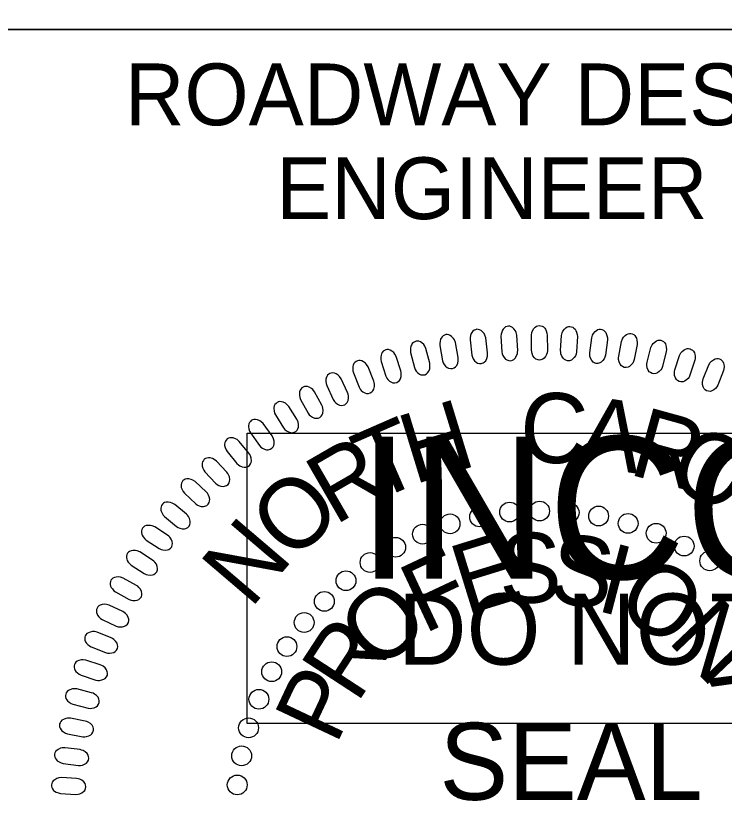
# Model space of a CAD drawing. Extents: x 505602 to 507286, y 483109 to 484209.
# Drawn here: x 507076.9 to 507134.2, y 484096 to 484159.8 of the extents above; entities that cross this region are included whole.
import ezdxf

# ---------------------------------------------------------------- set-up
doc = ezdxf.new("R2010")
doc.units = 0
for name, color, linetype in [('Sheet PE Seal Cell', 7, 'Continuous'), ('Sheet Profile CELL', 7, 'Continuous'), ('Sheet Sticker Incomplete CELL', 7, 'Continuous')]:
    doc.layers.add(name, color=color, linetype=linetype)

msp = doc.modelspace()

# ---------------------------------------------------------------- linework, layer by layer
at = {"layer": 'Sheet PE Seal Cell'}
for points in [[(507115.061, 484132.495), (507114.908, 484133.712), (507114.844, 484133.925), (507114.774, 484134.057), (507114.642, 484134.211), (507114.531, 484134.308), (507114.411, 484134.373), (507114.301, 484134.399), (507114.187, 484134.405), (507114.079, 484134.371), (507113.964, 484134.327), (507113.868, 484134.254), (507113.776, 484134.142), (507113.727, 484134.056), (507113.679, 484133.899), (507113.642, 484133.713), (507113.64, 484133.552), (507113.79, 484132.305), (507113.833, 484132.139), (507113.895, 484132.006), (507114.003, 484131.859), (507114.132, 484131.735), (507114.239, 484131.668), (507114.402, 484131.627), (507114.553, 484131.626), (507114.696, 484131.685), (507114.794, 484131.748), (507114.907, 484131.862), (507115.005, 484132.045), (507115.049, 484132.232), (507115.062, 484132.364)], [(507117.5, 484132.697), (507117.423, 484133.922), (507117.372, 484134.138), (507117.311, 484134.274), (507117.188, 484134.437), (507117.085, 484134.54), (507116.968, 484134.613), (507116.861, 484134.646), (507116.747, 484134.659), (507116.637, 484134.632), (507116.52, 484134.595), (507116.419, 484134.529), (507116.321, 484134.422), (507116.266, 484134.339), (507116.208, 484134.185), (507116.159, 484134.003), (507116.147, 484133.842), (507116.218, 484132.587), (507116.251, 484132.42), (507116.305, 484132.283), (507116.404, 484132.129), (507116.525, 484131.997), (507116.626, 484131.923), (507116.787, 484131.873), (507116.938, 484131.863), (507117.085, 484131.912), (507117.186, 484131.969), (507117.306, 484132.076), (507117.415, 484132.252), (507117.471, 484132.436), (507117.493, 484132.567)], [(507118.615, 484132.706), (507118.615, 484133.933), (507118.653, 484134.152), (507118.705, 484134.293), (507118.817, 484134.462), (507118.915, 484134.571), (507119.027, 484134.651), (507119.131, 484134.691), (507119.244, 484134.711), (507119.355, 484134.691), (507119.475, 484134.661), (507119.58, 484134.601), (507119.684, 484134.501), (507119.744, 484134.421), (507119.811, 484134.272), (507119.871, 484134.092), (507119.894, 484133.933), (507119.901, 484132.676), (507119.878, 484132.507), (507119.833, 484132.367), (507119.744, 484132.208), (507119.631, 484132.067), (507119.534, 484131.988), (507119.377, 484131.928), (507119.228, 484131.909), (507119.078, 484131.948), (507118.974, 484131.998), (507118.846, 484132.098), (507118.727, 484132.268), (507118.66, 484132.447), (507118.63, 484132.577)], [(507120.974, 484132.68), (507121.051, 484133.904), (507121.102, 484134.121), (507121.163, 484134.257), (507121.286, 484134.419), (507121.39, 484134.522), (507121.507, 484134.595), (507121.614, 484134.628), (507121.727, 484134.641), (507121.838, 484134.614), (507121.955, 484134.576), (507122.056, 484134.51), (507122.154, 484134.404), (507122.209, 484134.321), (507122.267, 484134.167), (507122.315, 484133.984), (507122.327, 484133.824), (507122.255, 484132.569), (507122.222, 484132.401), (507122.169, 484132.265), (507122.069, 484132.111), (507121.948, 484131.979), (507121.846, 484131.905), (507121.686, 484131.855), (507121.535, 484131.845), (507121.389, 484131.894), (507121.287, 484131.951), (507121.167, 484132.058), (507121.059, 484132.235), (507121.002, 484132.418), (507120.981, 484132.55)], [(507123.336, 484132.505), (507123.491, 484133.722), (507123.555, 484133.935), (507123.625, 484134.066), (507123.757, 484134.221), (507123.868, 484134.318), (507123.989, 484134.382), (507124.097, 484134.409), (507124.211, 484134.415), (507124.32, 484134.38), (507124.434, 484134.336), (507124.531, 484134.263), (507124.622, 484134.151), (507124.672, 484134.065), (507124.72, 484133.908), (507124.756, 484133.722), (507124.759, 484133.561), (507124.608, 484132.313), (507124.564, 484132.148), (507124.503, 484132.016), (507124.394, 484131.868), (507124.265, 484131.744), (507124.159, 484131.677), (507123.995, 484131.637), (507123.844, 484131.636), (507123.701, 484131.695), (507123.603, 484131.757), (507123.489, 484131.872), (507123.392, 484132.055), (507123.348, 484132.242), (507123.335, 484132.375)], [(507112.68, 484132.127), (507112.451, 484133.331), (507112.373, 484133.54), (507112.296, 484133.668), (507112.153, 484133.813), (507112.038, 484133.903), (507111.913, 484133.96), (507111.803, 484133.98), (507111.688, 484133.979), (507111.582, 484133.938), (507111.47, 484133.886), (507111.378, 484133.808), (507111.294, 484133.69), (507111.25, 484133.6), (507111.213, 484133.441), (507111.187, 484133.254), (507111.195, 484133.093), (507111.423, 484131.857), (507111.476, 484131.694), (507111.546, 484131.566), (507111.665, 484131.426), (507111.801, 484131.309), (507111.911, 484131.249), (507112.077, 484131.22), (507112.227, 484131.229), (507112.367, 484131.296), (507112.46, 484131.364), (507112.566, 484131.486), (507112.652, 484131.674), (507112.685, 484131.864), (507112.689, 484131.996)], [(507125.676, 484132.219), (507125.906, 484133.423), (507125.984, 484133.632), (507126.062, 484133.759), (507126.204, 484133.904), (507126.319, 484133.994), (507126.444, 484134.051), (507126.555, 484134.071), (507126.669, 484134.07), (507126.775, 484134.029), (507126.887, 484133.977), (507126.979, 484133.898), (507127.063, 484133.781), (507127.106, 484133.692), (507127.144, 484133.532), (507127.17, 484133.344), (507127.162, 484133.183), (507126.933, 484131.947), (507126.879, 484131.785), (507126.809, 484131.657), (507126.691, 484131.517), (507126.554, 484131.401), (507126.444, 484131.34), (507126.279, 484131.311), (507126.128, 484131.32), (507125.989, 484131.387), (507125.896, 484131.455), (507125.789, 484131.577), (507125.704, 484131.766), (507125.671, 484131.955), (507125.666, 484132.088)], [(507110.375, 484131.654), (507110.07, 484132.843), (507109.98, 484133.046), (507109.894, 484133.169), (507109.743, 484133.305), (507109.622, 484133.387), (507109.494, 484133.436), (507109.382, 484133.449), (507109.269, 484133.441), (507109.165, 484133.394), (507109.057, 484133.335), (507108.97, 484133.251), (507108.893, 484133.128), (507108.855, 484133.036), (507108.827, 484132.874), (507108.814, 484132.686), (507108.832, 484132.526), (507109.137, 484131.306), (507109.2, 484131.148), (507109.279, 484131.024), (507109.405, 484130.891), (507109.549, 484130.784), (507109.662, 484130.731), (507109.83, 484130.711), (507109.979, 484130.73), (507110.114, 484130.805), (507110.203, 484130.879), (507110.301, 484131.008), (507110.375, 484131.202), (507110.396, 484131.393), (507110.392, 484131.525)], [(507127.981, 484131.745), (507128.286, 484132.933), (507128.377, 484133.135), (507128.463, 484133.258), (507128.614, 484133.395), (507128.735, 484133.476), (507128.863, 484133.526), (507128.975, 484133.538), (507129.089, 484133.53), (507129.192, 484133.483), (507129.3, 484133.424), (507129.387, 484133.34), (507129.463, 484133.217), (507129.501, 484133.125), (507129.529, 484132.963), (507129.543, 484132.775), (507129.525, 484132.614), (507129.219, 484131.395), (507129.154, 484131.237), (507129.076, 484131.113), (507128.95, 484130.981), (507128.806, 484130.873), (507128.693, 484130.82), (507128.526, 484130.801), (507128.376, 484130.819), (507128.241, 484130.896), (507128.152, 484130.97), (507128.054, 484131.098), (507127.98, 484131.292), (507127.96, 484131.482), (507127.963, 484131.615)], [(507108.041, 484131.034), (507107.662, 484132.201), (507107.56, 484132.398), (507107.467, 484132.514), (507107.308, 484132.641), (507107.181, 484132.716), (507107.05, 484132.757), (507106.938, 484132.763), (507106.825, 484132.747), (507106.724, 484132.694), (507106.621, 484132.628), (507106.539, 484132.539), (507106.47, 484132.412), (507106.438, 484132.317), (507106.42, 484132.154), (507106.419, 484131.965), (507106.447, 484131.806), (507106.827, 484130.609), (507106.901, 484130.454), (507106.987, 484130.336), (507107.121, 484130.211), (507107.271, 484130.113), (507107.388, 484130.067), (507107.556, 484130.059), (507107.704, 484130.086), (507107.834, 484130.17), (507107.919, 484130.25), (507108.009, 484130.384), (507108.07, 484130.582), (507108.079, 484130.774), (507108.067, 484130.906)], [(507130.231, 484131.122), (507130.61, 484132.289), (507130.714, 484132.487), (507130.807, 484132.603), (507130.966, 484132.73), (507131.092, 484132.803), (507131.223, 484132.845), (507131.335, 484132.85), (507131.448, 484132.835), (507131.549, 484132.781), (507131.653, 484132.715), (507131.735, 484132.626), (507131.803, 484132.499), (507131.835, 484132.405), (507131.853, 484132.242), (507131.854, 484132.052), (507131.826, 484131.894), (507131.444, 484130.697), (507131.371, 484130.542), (507131.285, 484130.423), (507131.15, 484130.299), (507131, 484130.201), (507130.883, 484130.155), (507130.715, 484130.147), (507130.567, 484130.175), (507130.437, 484130.258), (507130.353, 484130.338), (507130.263, 484130.472), (507130.202, 484130.67), (507130.193, 484130.862), (507130.205, 484130.995)], [(507105.84, 484130.217), (507105.389, 484131.358), (507105.273, 484131.549), (507105.174, 484131.659), (507105.007, 484131.776), (507104.876, 484131.842), (507104.743, 484131.875), (507104.631, 484131.873), (507104.519, 484131.85), (507104.422, 484131.79), (507104.322, 484131.719), (507104.247, 484131.625), (507104.186, 484131.494), (507104.16, 484131.398), (507104.152, 484131.234), (507104.163, 484131.045), (507104.2, 484130.888), (507104.656, 484129.717), (507104.739, 484129.568), (507104.832, 484129.454), (507104.974, 484129.339), (507105.13, 484129.25), (507105.249, 484129.211), (507105.418, 484129.214), (507105.564, 484129.251), (507105.688, 484129.343), (507105.767, 484129.427), (507105.849, 484129.567), (507105.898, 484129.768), (507105.894, 484129.96), (507105.874, 484130.092)], [(507132.514, 484130.388), (507132.966, 484131.528), (507133.082, 484131.718), (507133.182, 484131.829), (507133.349, 484131.945), (507133.48, 484132.011), (507133.613, 484132.044), (507133.725, 484132.043), (507133.837, 484132.02), (507133.933, 484131.96), (507134.034, 484131.888), (507134.109, 484131.794), (507134.17, 484131.662), (507134.196, 484131.566), (507134.203, 484131.403), (507134.193, 484131.214), (507134.155, 484131.057), (507133.699, 484129.886), (507133.615, 484129.737), (507133.522, 484129.623), (507133.38, 484129.509), (507133.224, 484129.419), (507133.105, 484129.381), (507132.936, 484129.384), (507132.79, 484129.421), (507132.666, 484129.512), (507132.587, 484129.597), (507132.505, 484129.737), (507132.457, 484129.939), (507132.46, 484130.13), (507132.481, 484130.262)], [(507103.723, 484129.285), (507103.201, 484130.395), (507103.074, 484130.577), (507102.967, 484130.682), (507102.794, 484130.788), (507102.659, 484130.845), (507102.523, 484130.87), (507102.412, 484130.861), (507102.302, 484130.832), (507102.209, 484130.766), (507102.113, 484130.688), (507102.044, 484130.59), (507101.992, 484130.455), (507101.972, 484130.357), (507101.974, 484130.193), (507101.997, 484130.005), (507102.044, 484129.851), (507102.572, 484128.711), (507102.665, 484128.567), (507102.765, 484128.46), (507102.914, 484128.354), (507103.075, 484128.275), (507103.196, 484128.244), (507103.364, 484128.257), (507103.508, 484128.302), (507103.626, 484128.402), (507103.7, 484128.492), (507103.772, 484128.636), (507103.808, 484128.84), (507103.793, 484129.031), (507103.765, 484129.161)], [(507101.64, 484128.271), (507101.049, 484129.346), (507100.911, 484129.521), (507100.798, 484129.618), (507100.618, 484129.712), (507100.48, 484129.762), (507100.343, 484129.778), (507100.233, 484129.762), (507100.124, 484129.726), (507100.036, 484129.655), (507099.945, 484129.571), (507099.882, 484129.468), (507099.839, 484129.33), (507099.825, 484129.231), (507099.837, 484129.068), (507099.872, 484128.881), (507099.929, 484128.731), (507100.528, 484127.626), (507100.628, 484127.488), (507100.735, 484127.387), (507100.89, 484127.291), (507101.056, 484127.222), (507101.18, 484127.199), (507101.346, 484127.222), (507101.486, 484127.277), (507101.599, 484127.383), (507101.666, 484127.477), (507101.73, 484127.626), (507101.753, 484127.832), (507101.726, 484128.022), (507101.689, 484128.15)], [(507099.622, 484127.129), (507098.965, 484128.165), (507098.816, 484128.33), (507098.698, 484128.42), (507098.512, 484128.504), (507098.371, 484128.544), (507098.234, 484128.551), (507098.124, 484128.529), (507098.019, 484128.485), (507097.934, 484128.409), (507097.85, 484128.319), (507097.793, 484128.213), (507097.758, 484128.073), (507097.751, 484127.973), (507097.774, 484127.811), (507097.82, 484127.627), (507097.886, 484127.48), (507098.553, 484126.415), (507098.662, 484126.284), (507098.775, 484126.19), (507098.937, 484126.103), (507099.106, 484126.045), (507099.23, 484126.03), (507099.395, 484126.064), (507099.532, 484126.127), (507099.637, 484126.24), (507099.699, 484126.339), (507099.753, 484126.491), (507099.763, 484126.698), (507099.723, 484126.886), (507099.679, 484127.011)], [(507097.622, 484125.774), (507096.901, 484126.767), (507096.742, 484126.922), (507096.618, 484127.005), (507096.427, 484127.076), (507096.284, 484127.108), (507096.147, 484127.106), (507096.038, 484127.077), (507095.936, 484127.027), (507095.857, 484126.946), (507095.778, 484126.851), (507095.728, 484126.741), (507095.702, 484126.599), (507095.7, 484126.499), (507095.734, 484126.338), (507095.791, 484126.158), (507095.867, 484126.016), (507096.599, 484124.995), (507096.717, 484124.871), (507096.835, 484124.784), (507097.001, 484124.707), (507097.174, 484124.66), (507097.3, 484124.653), (507097.462, 484124.697), (507097.594, 484124.769), (507097.692, 484124.889), (507097.747, 484124.99), (507097.792, 484125.146), (507097.789, 484125.353), (507097.738, 484125.538), (507097.686, 484125.661)], [(507095.741, 484124.385), (507094.959, 484125.331), (507094.791, 484125.476), (507094.662, 484125.55), (507094.468, 484125.609), (507094.323, 484125.632), (507094.185, 484125.622), (507094.08, 484125.586), (507093.98, 484125.53), (507093.906, 484125.443), (507093.834, 484125.344), (507093.79, 484125.231), (507093.774, 484125.087), (507093.778, 484124.988), (507093.822, 484124.829), (507093.89, 484124.653), (507093.975, 484124.515), (507094.769, 484123.543), (507094.895, 484123.426), (507095.018, 484123.347), (507095.189, 484123.282), (507095.364, 484123.245), (507095.49, 484123.246), (507095.649, 484123.3), (507095.777, 484123.38), (507095.867, 484123.506), (507095.916, 484123.611), (507095.95, 484123.768), (507095.934, 484123.975), (507095.872, 484124.156), (507095.812, 484124.276)], [(507093.954, 484122.846), (507093.114, 484123.741), (507092.937, 484123.875), (507092.803, 484123.942), (507092.605, 484123.988), (507092.46, 484124.002), (507092.323, 484123.983), (507092.219, 484123.941), (507092.124, 484123.879), (507092.056, 484123.787), (507091.989, 484123.683), (507091.954, 484123.568), (507091.946, 484123.424), (507091.956, 484123.325), (507092.01, 484123.17), (507092.089, 484122.998), (507092.181, 484122.867), (507093.037, 484121.945), (507093.169, 484121.836), (507093.297, 484121.766), (507093.472, 484121.711), (507093.65, 484121.685), (507093.775, 484121.693), (507093.93, 484121.757), (507094.053, 484121.845), (507094.134, 484121.977), (507094.177, 484122.085), (507094.201, 484122.244), (507094.173, 484122.449), (507094.098, 484122.627), (507094.032, 484122.741)], [(507092.291, 484121.237), (507091.398, 484122.077), (507091.212, 484122.2), (507091.074, 484122.257), (507090.874, 484122.292), (507090.728, 484122.296), (507090.592, 484122.269), (507090.492, 484122.22), (507090.401, 484122.152), (507090.339, 484122.057), (507090.278, 484121.949), (507090.25, 484121.832), (507090.251, 484121.687), (507090.268, 484121.589), (507090.331, 484121.437), (507090.421, 484121.271), (507090.522, 484121.145), (507091.433, 484120.279), (507091.571, 484120.18), (507091.704, 484120.117), (507091.882, 484120.073), (507092.06, 484120.059), (507092.185, 484120.075), (507092.336, 484120.148), (507092.453, 484120.244), (507092.526, 484120.38), (507092.561, 484120.49), (507092.576, 484120.652), (507092.534, 484120.855), (507092.45, 484121.027), (507092.376, 484121.137)], [(507090.678, 484119.45), (507089.733, 484120.232), (507089.54, 484120.343), (507089.399, 484120.392), (507089.197, 484120.414), (507089.051, 484120.409), (507088.918, 484120.373), (507088.821, 484120.318), (507088.734, 484120.244), (507088.677, 484120.146), (507088.625, 484120.034), (507088.603, 484119.916), (507088.614, 484119.771), (507088.637, 484119.674), (507088.709, 484119.527), (507088.81, 484119.366), (507088.918, 484119.248), (507089.881, 484118.441), (507090.026, 484118.349), (507090.162, 484118.295), (507090.343, 484118.263), (507090.521, 484118.26), (507090.645, 484118.284), (507090.791, 484118.367), (507090.901, 484118.469), (507090.966, 484118.61), (507090.995, 484118.722), (507090.999, 484118.884), (507090.945, 484119.084), (507090.849, 484119.25), (507090.768, 484119.356)], [(507089.153, 484117.748), (507088.123, 484118.414), (507087.918, 484118.501), (507087.773, 484118.533), (507087.57, 484118.531), (507087.425, 484118.509), (507087.297, 484118.458), (507087.207, 484118.392), (507087.129, 484118.308), (507087.085, 484118.203), (507087.046, 484118.086), (507087.038, 484117.966), (507087.066, 484117.824), (507087.1, 484117.731), (507087.189, 484117.593), (507087.308, 484117.445), (507087.429, 484117.34), (507088.481, 484116.652), (507088.635, 484116.578), (507088.777, 484116.541), (507088.96, 484116.529), (507089.138, 484116.548), (507089.258, 484116.586), (507089.393, 484116.686), (507089.491, 484116.8), (507089.538, 484116.947), (507089.553, 484117.062), (507089.539, 484117.223), (507089.461, 484117.415), (507089.347, 484117.569), (507089.254, 484117.665)], [(507087.939, 484115.725), (507086.904, 484116.382), (507086.699, 484116.469), (507086.553, 484116.5), (507086.349, 484116.496), (507086.204, 484116.472), (507086.077, 484116.421), (507085.987, 484116.354), (507085.91, 484116.269), (507085.867, 484116.164), (507085.828, 484116.047), (507085.822, 484115.927), (507085.851, 484115.785), (507085.886, 484115.692), (507085.976, 484115.554), (507086.095, 484115.408), (507086.218, 484115.304), (507087.275, 484114.624), (507087.43, 484114.552), (507087.572, 484114.515), (507087.755, 484114.505), (507087.933, 484114.525), (507088.052, 484114.564), (507088.187, 484114.665), (507088.284, 484114.78), (507088.33, 484114.927), (507088.344, 484115.043), (507088.328, 484115.204), (507088.25, 484115.395), (507088.134, 484115.548), (507088.04, 484115.643)], [(507086.636, 484113.676), (507085.561, 484114.267), (507085.351, 484114.34), (507085.203, 484114.362), (507085, 484114.345), (507084.857, 484114.313), (507084.733, 484114.254), (507084.648, 484114.181), (507084.576, 484114.092), (507084.54, 484113.984), (507084.509, 484113.865), (507084.51, 484113.745), (507084.548, 484113.605), (507084.589, 484113.514), (507084.687, 484113.383), (507084.816, 484113.244), (507084.945, 484113.147), (507086.042, 484112.535), (507086.201, 484112.473), (507086.345, 484112.445), (507086.528, 484112.447), (507086.705, 484112.477), (507086.822, 484112.524), (507086.95, 484112.633), (507087.039, 484112.755), (507087.076, 484112.905), (507087.083, 484113.02), (507087.057, 484113.18), (507086.966, 484113.366), (507086.841, 484113.511), (507086.742, 484113.6)], [(507085.527, 484111.552), (507084.417, 484112.075), (507084.203, 484112.135), (507084.054, 484112.147), (507083.853, 484112.117), (507083.712, 484112.076), (507083.592, 484112.009), (507083.511, 484111.931), (507083.446, 484111.838), (507083.416, 484111.728), (507083.392, 484111.607), (507083.401, 484111.488), (507083.447, 484111.35), (507083.494, 484111.262), (507083.601, 484111.137), (507083.738, 484111.006), (507083.872, 484110.918), (507085.007, 484110.376), (507085.169, 484110.324), (507085.314, 484110.306), (507085.497, 484110.319), (507085.671, 484110.361), (507085.784, 484110.414), (507085.906, 484110.531), (507085.988, 484110.658), (507086.015, 484110.81), (507086.014, 484110.926), (507085.978, 484111.083), (507085.876, 484111.264), (507085.742, 484111.401), (507085.637, 484111.483)], [(507084.587, 484109.433), (507083.447, 484109.885), (507083.229, 484109.931), (507083.08, 484109.934), (507082.881, 484109.892), (507082.743, 484109.842), (507082.628, 484109.767), (507082.553, 484109.684), (507082.492, 484109.588), (507082.47, 484109.476), (507082.454, 484109.354), (507082.47, 484109.235), (507082.525, 484109.101), (507082.577, 484109.016), (507082.691, 484108.898), (507082.836, 484108.777), (507082.976, 484108.697), (507084.141, 484108.227), (507084.307, 484108.186), (507084.454, 484108.176), (507084.635, 484108.2), (507084.806, 484108.253), (507084.916, 484108.314), (507085.03, 484108.438), (507085.103, 484108.569), (507085.121, 484108.723), (507085.113, 484108.839), (507085.068, 484108.994), (507084.954, 484109.167), (507084.812, 484109.296), (507084.702, 484109.372)], [(507083.712, 484107.244), (507082.545, 484107.623), (507082.325, 484107.655), (507082.176, 484107.649), (507081.98, 484107.595), (507081.845, 484107.536), (507081.735, 484107.454), (507081.665, 484107.368), (507081.611, 484107.267), (507081.596, 484107.154), (507081.587, 484107.031), (507081.611, 484106.914), (507081.674, 484106.783), (507081.732, 484106.701), (507081.853, 484106.591), (507082.005, 484106.479), (507082.15, 484106.408), (507083.342, 484106.011), (507083.51, 484105.981), (507083.657, 484105.981), (507083.837, 484106.016), (507084.004, 484106.08), (507084.111, 484106.147), (507084.216, 484106.278), (507084.281, 484106.414), (507084.289, 484106.569), (507084.274, 484106.683), (507084.219, 484106.836), (507084.094, 484107.001), (507083.944, 484107.121), (507083.83, 484107.19)], [(507083.007, 484104.988), (507081.819, 484105.294), (507081.598, 484105.312), (507081.449, 484105.297), (507081.257, 484105.23), (507081.126, 484105.163), (507081.021, 484105.075), (507080.957, 484104.983), (507080.909, 484104.879), (507080.9, 484104.766), (507080.9, 484104.642), (507080.931, 484104.526), (507081.002, 484104.4), (507081.064, 484104.322), (507081.193, 484104.219), (507081.352, 484104.118), (507081.501, 484104.056), (507082.716, 484103.735), (507082.886, 484103.715), (507083.032, 484103.724), (507083.209, 484103.771), (507083.372, 484103.845), (507083.474, 484103.919), (507083.571, 484104.056), (507083.627, 484104.196), (507083.626, 484104.351), (507083.603, 484104.465), (507083.539, 484104.613), (507083.404, 484104.77), (507083.247, 484104.88), (507083.128, 484104.941)], [(507082.496, 484102.693), (507081.291, 484102.923), (507081.069, 484102.927), (507080.921, 484102.903), (507080.734, 484102.824), (507080.608, 484102.749), (507080.508, 484102.654), (507080.45, 484102.559), (507080.409, 484102.453), (507080.408, 484102.339), (507080.415, 484102.215), (507080.453, 484102.102), (507080.532, 484101.98), (507080.599, 484101.906), (507080.733, 484101.812), (507080.899, 484101.719), (507081.051, 484101.667), (507082.284, 484101.424), (507082.455, 484101.415), (507082.601, 484101.433), (507082.774, 484101.491), (507082.932, 484101.574), (507083.029, 484101.655), (507083.117, 484101.798), (507083.165, 484101.941), (507083.154, 484102.096), (507083.124, 484102.208), (507083.05, 484102.351), (507082.906, 484102.501), (507082.742, 484102.6), (507082.62, 484102.654)], [(507082.076, 484100.378), (507080.859, 484100.532), (507080.636, 484100.523), (507080.491, 484100.489), (507080.309, 484100.399), (507080.187, 484100.317), (507080.094, 484100.215), (507080.042, 484100.116), (507080.008, 484100.007), (507080.014, 484099.894), (507080.028, 484099.771), (507080.074, 484099.66), (507080.161, 484099.544), (507080.232, 484099.474), (507080.372, 484099.389), (507080.542, 484099.307), (507080.698, 484099.264), (507081.944, 484099.099), (507082.115, 484099.1), (507082.259, 484099.127), (507082.428, 484099.196), (507082.581, 484099.29), (507082.672, 484099.377), (507082.752, 484099.524), (507082.79, 484099.671), (507082.769, 484099.823), (507082.733, 484099.934), (507082.65, 484100.072), (507082.497, 484100.212), (507082.327, 484100.302), (507082.202, 484100.347)], [(507081.789, 484098.034), (507080.565, 484098.112), (507080.343, 484098.088), (507080.2, 484098.045), (507080.024, 484097.944), (507079.908, 484097.854), (507079.822, 484097.747), (507079.776, 484097.645), (507079.749, 484097.534), (507079.762, 484097.421), (507079.784, 484097.3), (507079.837, 484097.192), (507079.93, 484097.081), (507080.006, 484097.016), (507080.151, 484096.94), (507080.326, 484096.868), (507080.484, 484096.836), (507081.738, 484096.749), (507081.908, 484096.761), (507082.05, 484096.797), (507082.215, 484096.877), (507082.362, 484096.979), (507082.448, 484097.071), (507082.517, 484097.224), (507082.546, 484097.372), (507082.516, 484097.524), (507082.473, 484097.632), (507082.382, 484097.765), (507082.22, 484097.895), (507082.045, 484097.974), (507081.917, 484098.011)]]:
    msp.add_lwpolyline(points, close=True, dxfattribs=at)
for centre in [(507116.843, 484119.611), (507119.272, 484119.69), (507121.661, 484119.569), (507114.414, 484119.213), (507124.049, 484119.29), (507112.025, 484118.656), (507126.438, 484118.691), (507109.796, 484117.82), (507128.707, 484117.894), (507130.976, 484116.857), (507107.621, 484116.76), (507133.046, 484115.662), (507105.55, 484115.525), (507103.599, 484114.052), (507101.847, 484112.379), (507100.214, 484110.667), (507098.82, 484108.715), (507097.585, 484106.684), (507096.549, 484104.453), (507095.712, 484102.143), (507095.154, 484099.873), (507094.795, 484097.522)]:
    msp.add_circle(centre, 0.801, dxfattribs=at)
at = {"layer": 'Sheet Profile CELL'}
for points in [[(507069.03, 484183.712), (507269.08, 484183.712), (507269.08, 484158.662), (507069.03, 484158.662)], [(507069.03, 484158.662), (507169.08, 484158.662), (507169.08, 484046.162), (507069.03, 484046.162)]]:
    msp.add_lwpolyline(points, close=True, dxfattribs=at)
at = {"layer": 'Sheet Sticker Incomplete CELL'}
msp.add_lwpolyline([(507095.597, 484102.505), (507095.597, 484126.005), (507242.597, 484126.005), (507242.597, 484102.505)], close=True, dxfattribs=at)

# ---------------------------------------------------------------- texts
at = {"layer": 'Sheet PE Seal Cell'}
for s, height, rotation, p in [('C', 5.669, 357.58768, (507117.59, 484123.701)), ('H', 5.669, 17.05575, (507109.084, 484121.818)), ('A', 5.669, 351.09832, (507122.165, 484123.493)), ('R', 5.669, 344.60896, (507126.371, 484122.698)), ('T', 5.669, 23.5451, (507105.906, 484120.408)), ('O', 5.669, 331.63025, (507129.326, 484122.044)), ('R', 5.669, 30.03446, (507102.685, 484118.489)), ('O', 5.669, 43.01317, (507099.209, 484115.46)), ('N', 5.669, 49.50253, (507095.863, 484111.705)), ('E', 5.669, 17.16862, (507113.281, 484111.248)), ('S', 5.669, 1.28903, (507116.048, 484112.208)), ('S', 5.669, 353.34923, (507119.909, 484112.309)), ('I', 5.669, 345.40944, (507123.709, 484111.678)), ('F', 5.669, 25.10842, (507109.891, 484109.71)), ('O', 5.669, 329.52984, (507125.213, 484111.506)), ('O', 5.669, 40.98802, (507106.194, 484106.571)), ('N', 5.669, 313.65025, (507129.525, 484109.202)), ('R', 5.669, 56.86761, (507104.48, 484104.025)), ('P', 5.669, 64.80741, (507102.793, 484100.663)), ('A', 5.669, 297.77065, (507132.862, 484106.121)), ('SEAL', 6.2363, 359.98136, (507111.164, 484096.314))]:
    msp.add_text(s, height=height, rotation=rotation, dxfattribs=at).set_placement(p)
at = {"layer": 'Sheet Profile CELL'}
for s, p in [('ROADWAY DESIGN', (507085.692, 484150.924)), ('ENGINEER', (507097.942, 484143.324))]:
    msp.add_text(s, height=5.0001, dxfattribs=at).set_placement(p)
at = {"layer": 'Sheet Sticker Incomplete CELL'}
for s, height, p in [('INCOMPLETE PLANS', 11.52, (507104.547, 484114.205)), ('DO NOT USE FOR R/W ACQUISITION', 5.76, (507107.797, 484107.255))]:
    msp.add_text(s, height=height, dxfattribs=at).set_placement(p)

doc.saveas('drawing.dxf')
